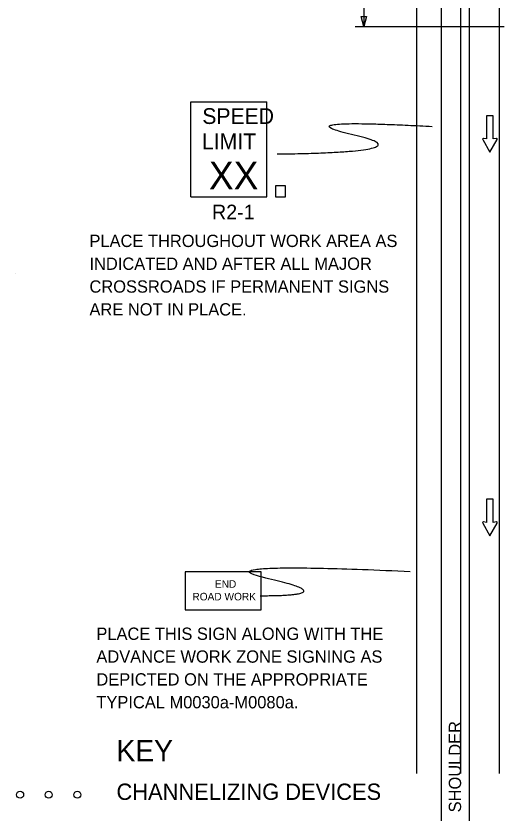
# Model space of a CAD drawing. Extents: x 16735 to 18475, y 6983 to 8262.
# Drawn here: x 16735.1 to 17012.9, y 7410.5 to 7864.5 of the extents above; entities that cross this region are included whole.
import ezdxf

# ---------------------------------------------------------------- set-up
doc = ezdxf.new("R2010")
doc.units = 0
for name, color, linetype in [('MT_SCRATCH_LEVEL_E', 7, 'Continuous'), ('PAVT_EDGE_EX', 7, 'Continuous'), ('TRAFFIC_SIGNS_PR', 7, 'Continuous'), ('TYPICAL_TEXT_DIMEN_EX', 7, 'Continuous'), ('TYPICAL_TEXT_DIMEN_PR', 7, 'Continuous')]:
    doc.layers.add(name, color=color, linetype=linetype)

msp = doc.modelspace()

# ---------------------------------------------------------------- linework, layer by layer
at = {"layer": 'MT_SCRATCH_LEVEL_E'}
for p, q in [((17006.75, 7807.71), (17003.01, 7807.71)), ((17003.01, 7807.71), (17003.01, 7794.46)), ((17006.75, 7807.71), (17003.01, 7807.71)), ((17003.01, 7807.71), (17003.01, 7794.46)), ((17006.75, 7794.46), (17006.75, 7807.71)), ((17006.75, 7794.46), (17006.75, 7807.71)), ((17000.75, 7794.09), (17004.9, 7786.85)), ((17000.75, 7794.09), (17004.9, 7786.85)), ((17003.01, 7794.46), (17001.23, 7794.77)), ((17003.01, 7794.46), (17001.23, 7794.77)), ((17004.9, 7786.85), (17009.01, 7794.09)), ((17004.9, 7786.85), (17009.01, 7794.09)), ((17008.53, 7794.77), (17006.75, 7794.46)), ((17008.53, 7794.77), (17006.75, 7794.46)), ((17006.75, 7589.33), (17003.01, 7589.33)), ((17003.01, 7589.33), (17003.01, 7576.07)), ((17006.75, 7589.33), (17003.01, 7589.33)), ((17003.01, 7589.33), (17003.01, 7576.07)), ((17006.75, 7576.07), (17006.75, 7589.33)), ((17006.75, 7576.07), (17006.75, 7589.33)), ((17000.75, 7575.7), (17004.9, 7568.46)), ((17000.75, 7575.7), (17004.9, 7568.46)), ((17003.01, 7576.07), (17001.23, 7576.38)), ((17003.01, 7576.07), (17001.23, 7576.38)), ((17004.9, 7568.46), (17009.01, 7575.7)), ((17004.9, 7568.46), (17009.01, 7575.7)), ((17008.53, 7576.38), (17006.75, 7576.07)), ((17008.53, 7576.38), (17006.75, 7576.07))]:
    msp.add_line(p, q, dxfattribs=at)
for centre, start, end in [((17001.16, 7794.31), 80.0362, 209.7731), ((17001.16, 7794.31), 80.0362, 209.7731), ((17008.6, 7794.31), 330.4248, 99.9638), ((17008.6, 7794.31), 330.4248, 99.9638), ((17001.16, 7575.92), 80.0362, 209.7731), ((17001.16, 7575.92), 80.0362, 209.7731), ((17008.6, 7575.92), 330.4248, 99.9638), ((17008.6, 7575.92), 330.4248, 99.9638)]:
    msp.add_arc(centre, 0.463, start, end, dxfattribs=at)
at = {"layer": 'PAVT_EDGE_EX'}
for p, q in [((16963.15, 8262.34), (16963.15, 7433.15)), ((16988.15, 8262.34), (16988.15, 7433.15)), ((17010.15, 8262.34), (17010.15, 7433.15)), ((16977.08, 8195.21), (16977.08, 7357.91)), ((16993.08, 8195.21), (16993.08, 7357.91))]:
    msp.add_line(p, q, dxfattribs=at)
at = {"layer": 'TRAFFIC_SIGNS_PR'}
for p, q in [((16834.69, 7815.52), (16877.89, 7815.52)), ((16834.69, 7761.52), (16834.69, 7815.52)), ((16877.89, 7761.52), (16877.89, 7815.52)), ((16834.69, 7761.52), (16877.89, 7761.52))]:
    msp.add_line(p, q, dxfattribs=at)
for points in [[(16882.91, 7761.52), (16888.5, 7761.52), (16888.5, 7767.69), (16882.91, 7767.69)], [(16831.48, 7526.32), (16874.68, 7526.32), (16874.68, 7547.92), (16831.48, 7547.92)]]:
    msp.add_lwpolyline(points, close=True, dxfattribs=at)
for centre in [(16737.48, 7420.97), (16753.78, 7420.97), (16770.08, 7420.97)]:
    msp.add_circle(centre, 2, dxfattribs=at)
for points in [[(16883.69, 7785.89), (16969.83, 7787.06), (16884.81, 7806.4), (16971.97, 7801.57)], [(16874.17, 7534.32), (16921.4, 7534.32), (16836.38, 7553.67), (16959.48, 7548.18)]]:
    msp.add_open_spline(points, degree=2, dxfattribs=at)
at = {"layer": 'TYPICAL_TEXT_DIMEN_PR'}
for p, q in [((16933.08, 7890.49), (16933.08, 7858.43)), ((16933.08, 7858.43), (16931.51, 7864.29)), ((16931.51, 7864.29), (16933.08, 7864.29)), ((16933.08, 7864.29), (16934.65, 7864.29)), ((16934.65, 7864.29), (16933.08, 7858.43)), ((16928.08, 7858.43), (17012.91, 7858.43))]:
    msp.add_line(p, q, dxfattribs=at)
msp.add_open_spline([(16735.12, 7717.93), (16735.13, 7717.93), (16735.13, 7717.93), (16735.13, 7717.93)], degree=2, dxfattribs=at)

# ---------------------------------------------------------------- texts
at = {"layer": 'TRAFFIC_SIGNS_PR'}
for s, height, p in [('SPEED', 9, (16841.18, 7802.99)), ('LIMIT', 9, (16841, 7788.59)), ('XX', 15.785, (16844.94, 7765.75)), ('R2-1', 8.37, (16846.7, 7748.65)), ('PLACE THROUGHOUT WORK AREA AS', 7, (16776.95, 7732.91)), ('INDICATED AND AFTER ALL MAJOR', 7, (16776.95, 7719.91)), ('CROSSROADS IF PERMANENT SIGNS', 7, (16776.95, 7706.91)), ('ARE NOT IN PLACE.', 7, (16776.95, 7693.91)), ('END', 4.31, (16848.36, 7538.84)), ('ROAD WORK', 4.31, (16835.54, 7531.65)), ('PLACE THIS SIGN ALONG WITH THE', 7, (16780.89, 7509.17)), ('ADVANCE WORK ZONE SIGNING AS', 7, (16780.89, 7496.17)), ('DEPICTED ON THE APPROPRIATE', 7, (16780.89, 7483.17)), ('TYPICAL M0030a-M0080a.', 7, (16780.89, 7470.17))]:
    msp.add_text(s, height=height, dxfattribs=at).set_placement(p)
at = {"layer": 'TYPICAL_TEXT_DIMEN_EX'}
for s, height, p in [('KEY', 12, (16792.33, 7440.08)), ('CHANNELIZING DEVICES', 9.3, (16792.33, 7418.03))]:
    msp.add_text(s, height=height, dxfattribs=at).set_placement(p)
at = {"layer": 'TYPICAL_TEXT_DIMEN_PR'}
msp.add_text('SHOULDER', height=7, rotation=90, dxfattribs=at).set_placement((16988.46, 7410.94))

doc.saveas('drawing.dxf')
